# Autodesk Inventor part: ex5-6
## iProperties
Shininess: 64.0
Length Units: 11272
Angle Units: 11279
Time Units: 11290
Mass Units: 11286
Length Display Precision: 3
Angle Display Precision: 2
Compacted: True
Part Number: ex5-6
Document SubType Name: Modeling
Created: 2003-11
Designer: Elise Moss
Cost Center: 0.1 lbmass
Authority: 1.78 in^3
Manufacturer: Standard
Standards Organization: Custom
Density: 0.0
Volumn: 0.0
Area: 0.0
PropertySet Name: Model Information
Control State: 0
Master: False
Checked Out: False
SaveDate: 2003-11-14
SaveTime: 17:44
TotalMass: 0.1 lbmass
TotalVolume: 1.78 in^3
Author: Elise Moss
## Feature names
1. Loft1
2. Shell1
